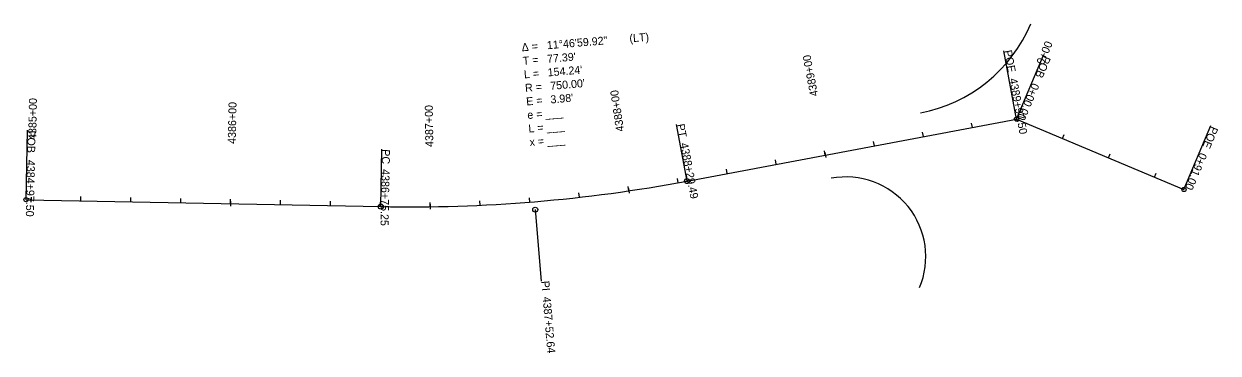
# Model space of a CAD drawing. Extents: x 14110369 to 14110967, y 8649374 to 8649539.
import ezdxf

# ---------------------------------------------------------------- set-up
doc = ezdxf.new("R2010")
doc.units = 0
for name, color, linetype in [('Alignment', 7, 'Continuous'), ('Default', 7, 'Continuous'), ('TextAlignment', 7, 'Continuous'), ('TextAlignmentLrg', 7, 'Continuous'), ('TextAlignmentSml', 7, 'Continuous')]:
    doc.layers.add(name, color=color, linetype=linetype)

msp = doc.modelspace()

# ---------------------------------------------------------------- linework, layer by layer
at = {"layer": 'Alignment'}
for p, q in [((14110700.94, 8649460.3), (14110866.05, 8649491.39)), ((14110866.05, 8649491.39), (14110949.91, 8649456.07)), ((14110369.79, 8649450.97), (14110547.5, 8649447.5))]:
    msp.add_line(p, q, dxfattribs=at)
for centre, radius, start, end in [((14110804.01, 8649568.24), 75, 280.6633, 337.1633), ((14110780.56, 8649422.38), 40, 337.1547, 100.6633), ((14110562.16, 8650197.35), 750, 268.87999, 280.6633)]:
    msp.add_arc(centre, radius, start, end, dxfattribs=at)
at = {"layer": 'Default'}
for p, q in [((14110700.94, 8649460.3), (14110866.05, 8649491.39)), ((14110369.79, 8649450.97), (14110547.5, 8649447.5))]:
    msp.add_line(p, q, dxfattribs=at)
msp.add_arc((14110562.16, 8650197.35), 750, 268.87999, 280.6633, dxfattribs=at)
at = {"layer": 'TextAlignment'}
for p, q in [((14110866.05, 8649491.39), (14110859.61, 8649525.59)), ((14110866.05, 8649491.39), (14110879.55, 8649523.46)), ((14110369.79, 8649450.97), (14110370.47, 8649485.76)), ((14110700.94, 8649460.3), (14110695.61, 8649488.61)), ((14110949.91, 8649456.07), (14110963.42, 8649488.15)), ((14110547.5, 8649447.5), (14110548.06, 8649476.29)), ((14110624.88, 8649445.98), (14110627.87, 8649410.11))]:
    msp.add_line(p, q, dxfattribs=at)
for centre, radius in [((14110866.05, 8649491.39), 1.07), ((14110866.05, 8649491.39), 1.07), ((14110700.94, 8649460.3), 1.25), ((14110949.91, 8649456.07), 1.07), ((14110369.79, 8649450.97), 1.07), ((14110547.5, 8649447.5), 1.25), ((14110624.88, 8649445.98), 1.25)]:
    msp.add_circle(centre, radius, dxfattribs=at)
at = {"layer": 'TextAlignmentLrg'}
for p, q in [((14110866.52, 8649492.52), (14110865.57, 8649490.26)), ((14110770.23, 8649473.35), (14110769.83, 8649475.5)), ((14110671.86, 8649455.42), (14110671.54, 8649457.58)), ((14110372.31, 8649452.15), (14110372.26, 8649449.7)), ((14110472.27, 8649448.97), (14110472.31, 8649451.15)), ((14110572.25, 8649447.42), (14110572.22, 8649449.6))]:
    msp.add_line(p, q, dxfattribs=at)
at = {"layer": 'TextAlignmentSml'}
for p, q in [((14110866.52, 8649492.52), (14110865.57, 8649490.26)), ((14110843.94, 8649487.23), (14110843.53, 8649489.38)), ((14110794.8, 8649477.98), (14110794.39, 8649480.12)), ((14110819.37, 8649482.6), (14110818.96, 8649484.75)), ((14110889.09, 8649481.69), (14110889.93, 8649483.7)), ((14110770, 8649474.55), (14110770.46, 8649472.15)), ((14110912.13, 8649471.99), (14110912.97, 8649474)), ((14110745.66, 8649468.73), (14110745.26, 8649470.87)), ((14110696.52, 8649459.49), (14110696.13, 8649461.64)), ((14110721.09, 8649464.1), (14110720.69, 8649466.25)), ((14110935.17, 8649462.28), (14110936.01, 8649464.3)), ((14110671.68, 8649456.63), (14110672.04, 8649454.21)), ((14110372.31, 8649452.15), (14110372.26, 8649449.7)), ((14110397.28, 8649450.43), (14110397.32, 8649452.62)), ((14110422.28, 8649449.94), (14110422.32, 8649452.13)), ((14110447.27, 8649449.46), (14110447.31, 8649451.64)), ((14110472.29, 8649450.19), (14110472.24, 8649447.74)), ((14110497.26, 8649448.48), (14110497.31, 8649450.66)), ((14110522.26, 8649447.99), (14110522.3, 8649450.17)), ((14110547.25, 8649447.5), (14110547.3, 8649449.68)), ((14110597.24, 8649448.17), (14110597.14, 8649450.35)), ((14110622.19, 8649449.76), (14110622.01, 8649451.94)), ((14110647.07, 8649452.17), (14110646.82, 8649454.34)), ((14110572.24, 8649448.64), (14110572.27, 8649446.2))]:
    msp.add_line(p, q, dxfattribs=at)

# ---------------------------------------------------------------- texts
at = {"layer": 'TextAlignment'}
for s, rotation, p in [(' (LT)', 4.77165, (14110670.76, 8649529.73)), ('Δ = ', 4.77165, (14110618.25, 8649525.35)), ('11°46\'59.92"', 4.77165, (14110630.9, 8649526.4)), ('T = ', 4.77165, (14110618.82, 8649518.56)), ("77.39'", 4.77165, (14110630.97, 8649519.57)), ('POE ', 280.6633, (14110859.68, 8649525.61)), ('POB ', 247.1633, (14110879.62, 8649523.43)), ('L = ', 4.77165, (14110619.39, 8649511.77)), ("154.24'", 4.77165, (14110631.29, 8649512.76)), ("750.00'", 4.77165, (14110632.58, 8649506.03)), ('4389+97.50', 280.6633, (14110862.34, 8649511.48)), ('R = ', 4.77165, (14110619.95, 8649504.98)), ("3.98'", 4.77165, (14110632.67, 8649499.2)), ('0+00.00', 247.1633, (14110873.88, 8649509.78)), ('E = ', 4.77165, (14110620.52, 8649498.19)), ('e = ___ ', 4.77165, (14110621.09, 8649491.4)), ('L = ___', 4.77165, (14110621.65, 8649484.61)), ('PT', 280.6633, (14110695.68, 8649488.62)), ('POE ', 247.1633, (14110963.49, 8649488.12)), ('POB ', 268.87999, (14110370.55, 8649485.76)), ('x = ___', 4.77165, (14110622.22, 8649477.82)), ('PC', 268.87999, (14110548.14, 8649476.29)), ('4388+29.49', 280.6633, (14110697.48, 8649479.09)), ('0+91.00', 247.1633, (14110957.91, 8649474.87)), ('4384+97.50', 268.87999, (14110370.26, 8649470.96)), ('4386+75.25', 268.87999, (14110547.95, 8649466.31)), ('PI ', 274.77165, (14110627.95, 8649410.11)), ('4387+52.64', 274.77165, (14110628.62, 8649402.15))]:
    msp.add_text(s, height=4.008, rotation=rotation, dxfattribs=at).set_placement(p)
at = {"layer": 'TextAlignmentLrg'}
for s, rotation, p in [('0+00', 67.1633, (14110879.54, 8649518.26)), ('4385+00', 88.87999, (14110374.88, 8649480.88))]:
    msp.add_text(s, height=4.008, rotation=rotation, dxfattribs=at).set_placement(p)
at = {"layer": 'TextAlignmentSml'}
for s, rotation, p in [('0+00', 67.1633, (14110879.54, 8649518.26)), ('4389+00', 100.6633, (14110766.65, 8649503.2)), ('4388+00', 98.4105, (14110669.45, 8649485.39)), ('4385+00', 88.87999, (14110374.88, 8649480.88)), ('4386+00', 88.87999, (14110474.86, 8649478.92)), ('4387+00', 90.77106, (14110573.85, 8649477.44))]:
    msp.add_text(s, height=4.008, rotation=rotation, dxfattribs=at).set_placement(p)

doc.saveas('drawing.dxf')
